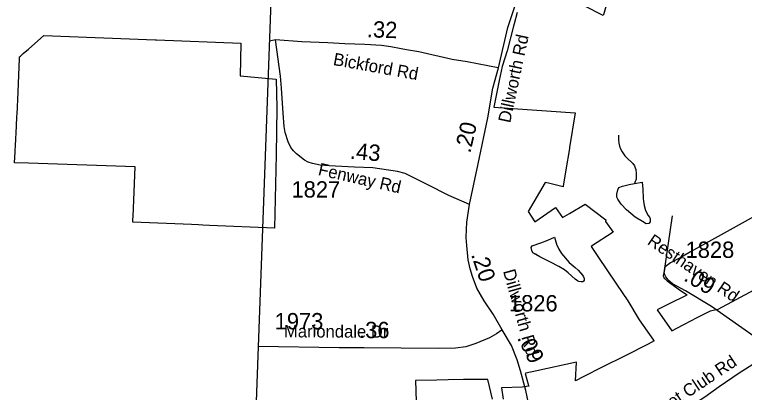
# Model space of a CAD drawing. Extents: x 1662474 to 1856135, y 779280 to 917889.
# Drawn here: x 1689895 to 1695471, y 832092 to 834982 of the extents above; entities that cross this region are included whole.
import ezdxf

# ---------------------------------------------------------------- set-up
doc = ezdxf.new("R2010")
doc.units = 0
for name, color, linetype in [('Exist Boundary Political City Limit New', 7, 'Continuous'), ('Exist Boundary Political City Limit New Hole', 7, 'Continuous'), ('Exist Boundary Political CountyLine', 7, 'Continuous'), ('Exist Hydrographic Misc Water Feature', 7, 'Continuous'), ('Exist Road Non-System Type 51', 7, 'Continuous'), ('Exist Road Secondary Mileage Hundredths English Label', 7, 'Continuous'), ('Exist Road Secondary Mileage Tenths English Label', 7, 'Continuous'), ('Exist Road Secondary Type 41 Attributed', 7, 'Continuous'), ('Exist Road Secondary Type 51 Attributed', 7, 'Continuous'), ('Exist Road Secondary Type 51 Label', 7, 'Continuous'), ('Exist Road Secondary Type 51 Number Label', 7, 'Continuous'), ('Map Preparation Boundary City Limit Buffer Line', 7, 'Continuous')]:
    doc.layers.add(name, color=color, linetype=linetype)

msp = doc.modelspace()

# ---------------------------------------------------------------- linework, layer by layer
at = {"layer": 'Exist Boundary Political City Limit New'}
for points in [[(1694539.1, 835485.7), (1694393.4, 834980.1), (1694391.9, 834974.7), (1693825.6, 835266.9)], [(1693734.5, 834997.9), (1693711.1, 834910.2), (1693706.9, 834894.4), (1693657.1, 834705.6), (1693620.9, 834585.7), (1693598.1, 834479.2), (1693555.4, 834274.4), (1694177.1, 834230.2), (1694134.1, 833964.3), (1694133.1, 833958.9), (1694106.5, 833794.6), (1694086.4, 833670.4), (1694085.5, 833664.9), (1693973.6, 833691.8), (1693947.4, 833698.1), (1693818, 833475.2), (1693870.4, 833397.4), (1694027.4, 833507.5), (1694079.9, 833429.6), (1694134.2, 833461.1), (1694255.2, 833531.4), (1694412.1, 833411.4), (1694410.2, 833400.1), (1694467.1, 833317.9), (1694303.4, 833209.7), (1694300.5, 833207.8), (1694351.1, 833130.7), (1694493.5, 832919.3), (1694578.8, 832792.7), (1694665.5, 832647.9)], [(1691892, 833908.7), (1691880.4, 833347.4), (1691384.6, 833369.2), (1691333.5, 833371.4), (1691300.6, 833372.9), (1691245.9, 833375.4), (1690797.9, 833395.4), (1690798.2, 833404.4), (1690798.6, 833414.4), (1690799.6, 833436.9), (1690807.4, 833627.4), (1690815.1, 833816.9), (1690000, 833844.6), (1689894.6, 833848.1), (1689898.9, 833933.1), (1689901.6, 833987.4), (1689902.2, 833999.4), (1689902.9, 834011.8), (1689904.1, 834038.1), (1689906, 834073.1), (1689912.4, 834197.1), (1689912.9, 834207.9), (1689913.4, 834218.9), (1689920.8, 834391.9), (1689931.6, 834645.9), (1689932.5, 834658.3), (1689939.5, 834664.4), (1689961.1, 834683.4), (1690000, 834717.5), (1690118.6, 834821.6), (1690967.6, 834788.4), (1690972.2, 834788.2), (1690979.8, 834787.9), (1691623.8, 834762.8), (1691619.2, 834512.4), (1691893.1, 834488.1), (1691899.4, 834268.7), (1691892, 833908.7)], [(1694665.5, 832647.9), (1694776.6, 832492.9), (1694781.6, 832485.9), (1694734.4, 832461.2), (1694559, 832371.9), (1694383.5, 832285.9), (1694243.2, 832213.7), (1694181.1, 832181), (1694186.9, 832324.4), (1693884.5, 832257.2), (1693799.9, 832238.6), (1693796.6, 832237.9), (1693821.8, 832145.5), (1693823, 832140.8), (1693771.6, 832131.4), (1693616.9, 832128.3), (1693614.1, 832128.2), (1693627.1, 832040.4)], [(1693547.1, 832039.4), (1693511.4, 832190.4), (1693323.9, 832189.9), (1693207.4, 832188.6), (1693120.9, 832186.9), (1692960, 832183.8), (1692957.9, 832183.7), (1692961.6, 832021.9)]]:
    msp.add_lwpolyline(points, dxfattribs=at)
at = {"layer": 'Exist Boundary Political City Limit New Hole'}
msp.add_lwpolyline([(1695779.9, 833568.1), (1695057.9, 833166.4), (1695001.9, 833135.3), (1694906.4, 833082.2), (1694875, 833059.1), (1694862.4, 833049.8), (1694853.8, 833002.2), (1694852.6, 832995.6), (1694850.6, 832984.9), (1694852.6, 832979.1), (1694855.4, 832970.9), (1694856.9, 832966.7), (1694865.1, 832959.8), (1694881.1, 832946.4), (1694983.5, 832871.6), (1695034.1, 832837.6), (1695026, 832833.6), (1694894.8, 832769), (1694803.8, 832724.2), (1694915.4, 832564.4), (1695001.9, 832609), (1695013.5, 832615), (1695108.6, 832664), (1695191.4, 832706.2), (1695211, 832716.2), (1695231.9, 832721), (1695269.8, 832729.6), (1695544.9, 832877.6)], dxfattribs=at)
at = {"layer": 'Exist Boundary Political CountyLine'}
msp.add_lwpolyline([(1693532.8, 878638.3), (1693519.9, 877349.9), (1693492, 876609.6), (1693453.8, 875667.6), (1693430.2, 875135.3), (1693375.3, 874115.3), (1693330.7, 873313.6), (1693283.8, 872475.6), (1693250.6, 871813.5), (1693208.1, 871017.3), (1693160.5, 870131.4), (1693122.4, 869369.3), (1693086.5, 868609.1), (1693046.7, 867715.1), (1693006.5, 866759), (1692985.5, 866061), (1692761.5, 860283.7), (1692552.7, 854372.1), (1692258.3, 846140.6), (1691699.3, 830912), (1691456.7, 824436.5)], dxfattribs=at)
at = {"layer": 'Exist Hydrographic Misc Water Feature'}
for points in [[(1694508.9, 834060.9), (1694508.5, 834023.3), (1694512.4, 833999.4), (1694516.8, 833974.6), (1694523.8, 833954.8), (1694535.7, 833933.2), (1694557.2, 833902.4), (1694580.9, 833878.1), (1694606.7, 833856.3), (1694618.9, 833842.9), (1694630.5, 833825.4), (1694636.3, 833809.7), (1694640.1, 833797.3), (1694642.1, 833787.4), (1694643.6, 833776.7), (1694644.6, 833762.8), (1694644.9, 833748), (1694643.4, 833723.4), (1694641.2, 833715.3), (1694637.1, 833705.5), (1694630.1, 833690)], [(1694630.1, 833690), (1694688.3, 833700.4), (1694693.5, 833646.1), (1694698.4, 833576.2), (1694700.3, 833554), (1694703.9, 833521.9), (1694715.4, 833484), (1694735.1, 833445.8), (1694746.7, 833431.6), (1694750.4, 833420.9), (1694750.2, 833403.7), (1694750.1, 833397.1), (1694740, 833383.3), (1694719.9, 833381.3), (1694692.4, 833398.3), (1694636.6, 833433.1), (1694569.5, 833489.4), (1694529.9, 833532.1), (1694518.1, 833546.3), (1694502.6, 833570.3), (1694496.8, 833584.4), (1694497, 833609.1), (1694503.4, 833640.9), (1694511.7, 833658.8), (1694539.8, 833670.6), (1694590, 833683.5), (1694630.1, 833690)], [(1694630.1, 833690), (1694688.3, 833700.4), (1694693.5, 833646.1), (1694698.4, 833576.2), (1694700.3, 833554), (1694703.9, 833521.9), (1694715.4, 833484), (1694735.1, 833445.8), (1694746.7, 833431.6), (1694750.4, 833420.9), (1694750.2, 833403.7), (1694750.1, 833397.1), (1694740, 833383.3), (1694719.9, 833381.3), (1694692.4, 833398.3), (1694636.6, 833433.1), (1694569.5, 833489.4), (1694529.9, 833532.1), (1694518.1, 833546.3), (1694502.6, 833570.3), (1694496.8, 833584.4), (1694497, 833609.1), (1694503.4, 833640.9), (1694511.7, 833658.8), (1694539.8, 833670.6), (1694590, 833683.5), (1694630.1, 833690)], [(1693967.8, 833257.9), (1694019.2, 833279.1), (1694034, 833227), (1694053.5, 833188), (1694073.1, 833154), (1694132.1, 833085.6), (1694177.7, 833048.5), (1694199.9, 833027.5), (1694225.1, 832998.3), (1694234.9, 832988.2), (1694241.9, 832977.4), (1694245.2, 832963.4), (1694246.3, 832951.9), (1694242.3, 832943.8), (1694236.8, 832939), (1694224.2, 832938.4), (1694204.9, 832941.3), (1694194.2, 832946.4), (1694176.8, 832959), (1694125.1, 833007.7), (1694095.3, 833028.9), (1694053.7, 833054.3), (1693990.1, 833087.6), (1693908.8, 833128.7), (1693894.8, 833136.3), (1693874.9, 833149.1), (1693855.3, 833160.9), (1693847.4, 833177.5), (1693841.7, 833201.4), (1693849.8, 833212.7), (1693914.1, 833236.1), (1693967.8, 833257.9)], [(1693967.8, 833257.9), (1694019.2, 833279.1), (1694034, 833227), (1694053.5, 833188), (1694073.1, 833154), (1694132.1, 833085.6), (1694177.7, 833048.5), (1694199.9, 833027.5), (1694234.9, 832988.2), (1694241.9, 832977.4), (1694245.2, 832963.4), (1694246.3, 832951.9), (1694242.3, 832943.8), (1694236.8, 832939), (1694224.2, 832938.4), (1694204.9, 832941.3), (1694194.2, 832946.4), (1694176.8, 832959), (1694125.1, 833007.7), (1694095.3, 833028.9), (1694053.7, 833054.3), (1693990.1, 833087.6), (1693908.8, 833128.7), (1693894.8, 833136.3), (1693855.3, 833160.9), (1693847.4, 833177.5), (1693841.7, 833201.4), (1693849.8, 833212.7), (1693914.1, 833236.1), (1693967.8, 833257.9)]]:
    msp.add_lwpolyline(points, dxfattribs=at)
at = {"layer": 'Exist Road Non-System Type 51'}
msp.add_lwpolyline([(1694888.1, 832950.5), (1694884, 832960.6), (1694871.4, 832975), (1694862.2, 832991.9), (1694857.2, 833007.2), (1694922.2, 833443.2)], dxfattribs=at)
at = {"layer": 'Exist Road Secondary Type 41 Attributed'}
msp.add_lwpolyline([(1695682.8, 832403), (1695635.9, 832449.8), (1695569.9, 832502.7), (1695426.8, 832603.9), (1695219.8, 832749.1), (1695019.4, 832868), (1694922.5, 832923), (1694888.1, 832950.5)], dxfattribs=at)
at = {"layer": 'Exist Road Secondary Type 51 Attributed'}
msp.add_line((1691888.8, 834788.2), (1691841.3, 834779.5), dxfattribs=at)
for points in [[(1693591.4, 834574.4), (1693663.5, 834882.4), (1693760.6, 835176.7), (1693826.1, 835343.2), (1693914.5, 835511.4), (1694024.8, 835715), (1694088.2, 835841.9), (1694108.3, 835912), (1694125, 836125.6), (1694148.4, 836651.7), (1694151.9, 836790.8), (1694145.7, 836915.2), (1694132.1, 837061.3), (1694111.5, 837256.6), (1694094.7, 837397.7), (1694071.7, 837541.9), (1694045.9, 837686.1), (1694016.4, 837791.1), (1693990.1, 837863.2), (1693963.9, 837918.9), (1693911.4, 838007.3)], [(1693370.4, 833529), (1693213.5, 833598.3), (1693047.2, 833682.3), (1692879.6, 833765.7), (1692820.3, 833781.5), (1692632, 833810.4), (1692491.3, 833813.9), (1692298.2, 833825.1), (1692228.9, 833831.3), (1692172, 833843.6), (1692138.1, 833854.4), (1692108.9, 833869.8), (1692047.8, 833916.3), (1692025.7, 833939), (1692006.3, 833966.5), (1691984.2, 834007.9), (1691962.6, 834079), (1691954.9, 834125.1), (1691945.7, 834227.9), (1691933.4, 834420.2), (1691927.2, 834511), (1691888.8, 834788.2)], [(1693590.1, 834573.6), (1693351.5, 834619.5), (1693238, 834639.7), (1692983.7, 834696.7), (1692888, 834712.6), (1692848.1, 834721.4), (1692770.4, 834735), (1692698.5, 834744.5), (1692570.6, 834753.1), (1692418.6, 834758.2), (1692286.7, 834766.8), (1692088.7, 834774.8), (1691888.8, 834788.2)], [(1693370.4, 833529), (1693435.4, 833841.6), (1693511.6, 834193.6), (1693549.3, 834420.5), (1693591.4, 834574.4)], [(1693620.9, 832571.8), (1693551.7, 832690.4), (1693481.1, 832793.8), (1693426.7, 832889.8), (1693393.4, 832979.5), (1693374.2, 833037.2), (1693361.2, 833105.6), (1693350.3, 833216.7), (1693345.7, 833278.1), (1693348, 833338.8), (1693349.9, 833394.7), (1693370.4, 833529)], [(1693620.9, 832571.8), (1693577.6, 832539.1), (1693523.2, 832509.5), (1693417.5, 832466.8), (1693342.9, 832441.2), (1693263.7, 832431.8), (1693131.9, 832427.9), (1692564.6, 832433.4), (1692375, 832434.2), (1691755.5, 832442.4)], [(1693968.5, 831249), (1693924.8, 831462), (1693903.2, 831578.5), (1693877.8, 831695.9), (1693821.9, 832009.4), (1693800.3, 832107.8), (1693760.6, 832258.5), (1693735, 832342.5), (1693691.5, 832450.2), (1693620.9, 832571.8)], [(1693968.5, 831249), (1694161.3, 831381.2), (1694358.1, 831513.2), (1694540.7, 831635.6), (1694694.9, 831740.5), (1694849.1, 831843.5), (1694985.1, 831936.8), (1695097.9, 832011.2), (1695167.6, 832057.1), (1695279.1, 832138), (1695430.9, 832241.8), (1695582.7, 832339.8), (1695644.5, 832380), (1695682.8, 832403)]]:
    msp.add_lwpolyline(points, dxfattribs=at)
at = {"layer": 'Map Preparation Boundary City Limit Buffer Line'}
for points in [[(1694539.1, 835485.7), (1694393.4, 834980.1), (1694391.9, 834974.7), (1693825.6, 835266.9)], [(1693734.5, 834997.9), (1693711.1, 834910.2), (1693706.9, 834894.4), (1693657.1, 834705.6), (1693620.9, 834585.7), (1693598.1, 834479.2), (1693555.4, 834274.4), (1694177.1, 834230.2), (1694134.1, 833964.3), (1694133.1, 833958.9), (1694106.5, 833794.6), (1694086.4, 833670.4), (1694085.5, 833664.9), (1693973.6, 833691.8), (1693947.4, 833698.1), (1693818, 833475.2), (1693870.4, 833397.4), (1694027.4, 833507.5), (1694079.9, 833429.6), (1694134.2, 833461.1), (1694255.2, 833531.4), (1694412.1, 833411.4), (1694410.2, 833400.1), (1694467.1, 833317.9), (1694303.4, 833209.7), (1694300.5, 833207.8), (1694351.1, 833130.7), (1694493.5, 832919.3), (1694578.8, 832792.7), (1694665.5, 832647.9)], [(1691892, 833908.7), (1691880.4, 833347.4), (1691384.6, 833369.2), (1691333.5, 833371.4), (1691300.6, 833372.9), (1691245.9, 833375.4), (1690797.9, 833395.4), (1690798.2, 833404.4), (1690798.6, 833414.4), (1690799.6, 833436.9), (1690807.4, 833627.4), (1690815.1, 833816.9), (1690000, 833844.6), (1689894.6, 833848.1), (1689898.9, 833933.1), (1689901.6, 833987.4), (1689902.2, 833999.4), (1689902.9, 834011.8), (1689904.1, 834038.1), (1689906, 834073.1), (1689912.4, 834197.1), (1689912.9, 834207.9), (1689913.4, 834218.9), (1689920.8, 834391.9), (1689931.6, 834645.9), (1689932.5, 834658.3), (1689939.5, 834664.4), (1689961.1, 834683.4), (1690000, 834717.5), (1690118.6, 834821.6), (1690967.6, 834788.4), (1690972.2, 834788.2), (1690979.8, 834787.9), (1691623.8, 834762.8), (1691619.2, 834512.4), (1691893.1, 834488.1), (1691899.4, 834268.7), (1691892, 833908.7)], [(1695779.9, 833568.1), (1695057.9, 833166.4), (1695001.9, 833135.3), (1694906.4, 833082.2), (1694875, 833059.1), (1694862.4, 833049.8), (1694853.8, 833002.2), (1694852.6, 832995.6), (1694850.6, 832984.9), (1694852.6, 832979.1), (1694855.4, 832970.9), (1694856.9, 832966.7), (1694865.1, 832959.8), (1694881.1, 832946.4), (1694983.5, 832871.6), (1695034.1, 832837.6), (1695026, 832833.6), (1694894.8, 832769), (1694803.8, 832724.2), (1694915.4, 832564.4), (1695001.9, 832609), (1695013.5, 832615), (1695108.6, 832664), (1695191.4, 832706.2), (1695211, 832716.2), (1695231.9, 832721), (1695269.8, 832729.6), (1695544.9, 832877.6)], [(1694665.5, 832647.9), (1694776.6, 832492.9), (1694781.6, 832485.9), (1694734.4, 832461.2), (1694559, 832371.9), (1694383.5, 832285.9), (1694243.2, 832213.7), (1694181.1, 832181), (1694186.9, 832324.4), (1693884.5, 832257.2), (1693799.9, 832238.6), (1693796.6, 832237.9), (1693821.8, 832145.5), (1693823, 832140.8), (1693771.6, 832131.4), (1693616.9, 832128.3), (1693614.1, 832128.2), (1693627.1, 832040.4)], [(1693547.1, 832039.4), (1693511.4, 832190.4), (1693323.9, 832189.9), (1693207.4, 832188.6), (1693120.9, 832186.9), (1692960, 832183.8), (1692957.9, 832183.7), (1692961.6, 832021.9)]]:
    msp.add_lwpolyline(points, dxfattribs=at)

# ---------------------------------------------------------------- texts
at = {"layer": 'Exist Road Secondary Mileage Hundredths English Label'}
for s, rotation, p in [('.32', 358.0776, (1692584.8, 834808.9)), ('.20', 77.0315, (1693376.5, 833917.6)), ('.43', 354.923, (1692453.4, 833879.9)), ('.09', 329.3288, (1695000, 832952.1)), ('.36', 359.8049, (1692526.5, 832507.5)), ('.09', 296.0422, (1693732.1, 832509.4))]:
    msp.add_text(s, height=125, rotation=rotation, dxfattribs=at).set_placement(p)
at = {"layer": 'Exist Road Secondary Mileage Tenths English Label'}
msp.add_text('.20', height=125, rotation=288.4447, dxfattribs=at).set_placement((1693380.9, 833146.8))
at = {"layer": 'Exist Road Secondary Type 51 Label'}
for s, rotation, p in [('Dillworth Rd', 78.0115, (1693681.1, 834148.6)), ('Bickford Rd', 349.7082, (1692323.6, 834597.4)), ('Fenway Rd', 347.1663, (1692208.3, 833756.3)), ('Resthaven Rd', 325.8031, (1694722.5, 833230.5)), ('Dillworth Rd', 285.6184, (1693625.7, 833020.2)), ('Mariondale Dr', 359.741, (1691952.6, 832513.3)), ('Skeet Club Rd', 33.6145, (1694739.3, 831850))]:
    msp.add_text(s, height=95, rotation=rotation, dxfattribs=at).set_placement(p)
at = {"layer": 'Exist Road Secondary Type 51 Number Label'}
for s, p in [('1827', (1692010.3, 833582.5)), ('1828', (1695021.3, 833121)), ('1826', (1693671.8, 832711.6)), ('1973', (1691881.8, 832574.4))]:
    msp.add_text(s, height=125, dxfattribs=at).set_placement(p)

doc.saveas('drawing.dxf')
